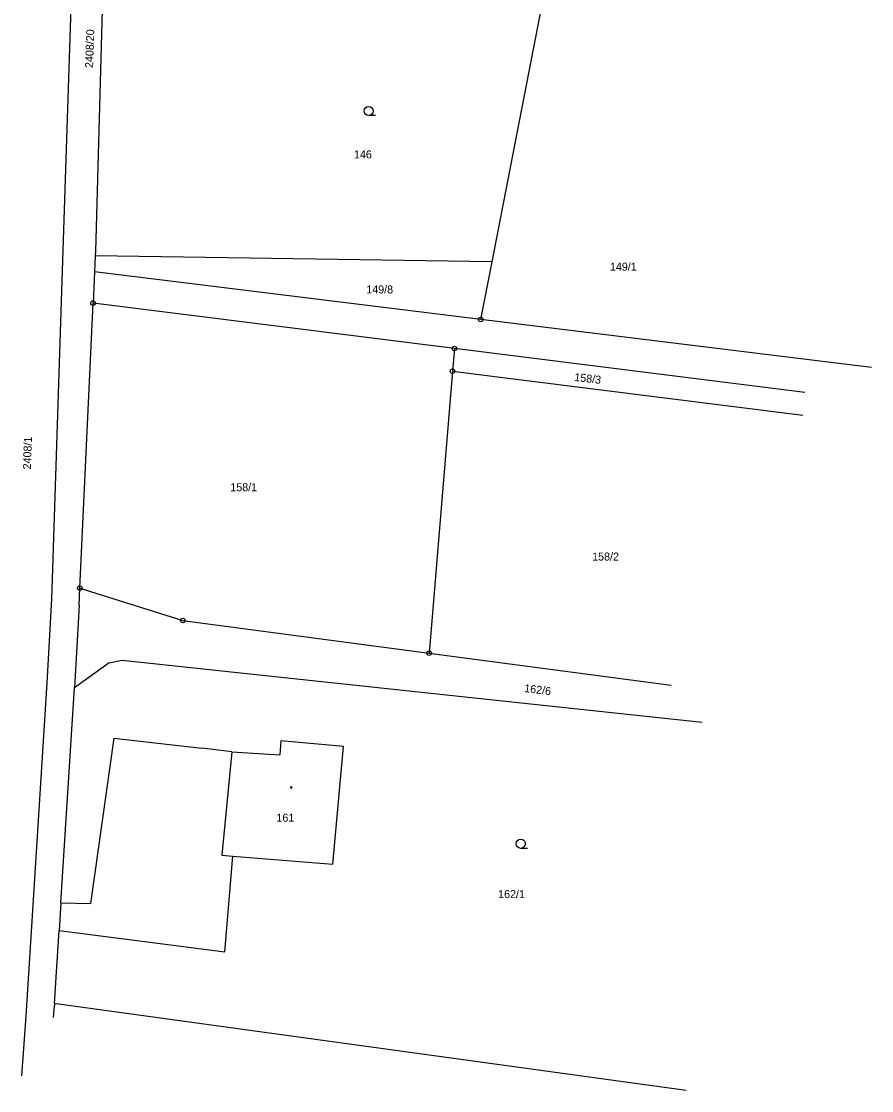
# Model space of a CAD drawing. Extents: x -454285 to -453563, y -1108687 to -1108249.
# Drawn here: x -453653.3 to -453578.9, y -1108665.2 to -1108571.7 of the extents above; entities that cross this region are included whole.
import ezdxf

# ---------------------------------------------------------------- set-up
doc = ezdxf.new("R2010")
doc.units = 0
for name, color, linetype in [('1', 7, 'Continuous'), ('14', 7, 'Continuous'), ('15', 7, 'Continuous'), ('16', 7, 'Continuous'), ('2', 7, 'Continuous'), ('23', 7, 'Continuous'), ('25', 7, 'Continuous'), ('28', 7, 'Continuous')]:
    doc.layers.add(name, color=color, linetype=linetype)

# ---------------------------------------------------------------- blocks, each defined once
blk = doc.blocks.new('Z402')
for start, end in [(0, 180), (180, 0)]:
    blk.add_arc((0, 0), 0.15, start, end)
blk = doc.blocks.new('Z105')
for radius in [0.5, 0.01]:
    blk.add_circle((0, 0), radius)
blk = doc.blocks.new('Z3040')
blk.add_line((1.5, 0), (0, 0))
blk.add_circle((0, 1), 1)

msp = doc.modelspace()

# ---------------------------------------------------------------- linework, layer by layer
at = {"layer": '1'}
for p, q in [((-453648.487, -1108555.791), (-453649.647, -1108591.661)), ((-453645.797, -1108555.891), (-453646.797, -1108591.781)), ((-453612.117, -1108592.681), (-453607.877, -1108570.931)), ((-453649.647, -1108591.661), (-453650.647, -1108622.191)), ((-453646.797, -1108591.781), (-453646.817, -1108592.171)), ((-453646.817, -1108592.171), (-453646.877, -1108593.571)), ((-453612.117, -1108592.681), (-453646.817, -1108592.171)), ((-453613.107, -1108597.731), (-453612.117, -1108592.681)), ((-453646.877, -1108593.571), (-453647.007, -1108596.291)), ((-453613.107, -1108597.731), (-453646.877, -1108593.571)), ((-453648.167, -1108621.231), (-453647.007, -1108596.291)), ((-453615.407, -1108600.261), (-453647.007, -1108596.291)), ((-453578.927, -1108601.941), (-453613.107, -1108597.731)), ((-453615.407, -1108600.261), (-453615.577, -1108602.251)), ((-453584.767, -1108604.111), (-453615.407, -1108600.261)), ((-453615.577, -1108602.251), (-453617.617, -1108626.911)), ((-453615.577, -1108602.251), (-453584.937, -1108606.101)), ((-453648.227, -1108622.701), (-453648.167, -1108621.231)), ((-453648.167, -1108621.231), (-453647.787, -1108621.351)), ((-453647.787, -1108621.351), (-453639.157, -1108624.051)), ((-453650.647, -1108622.191), (-453651.057, -1108629.511)), ((-453648.227, -1108622.701), (-453648.637, -1108629.941)), ((-453639.157, -1108624.051), (-453617.617, -1108626.911)), ((-453645.607, -1108627.761), (-453644.467, -1108627.531)), ((-453644.467, -1108627.531), (-453593.737, -1108632.961)), ((-453617.617, -1108626.911), (-453596.467, -1108629.721)), ((-453645.607, -1108627.761), (-453648.637, -1108629.941)), ((-453651.057, -1108629.511), (-453652.887, -1108658.661)), ((-453649.817, -1108648.741), (-453648.637, -1108629.941)), ((-453645.197, -1108634.341), (-453647.247, -1108648.801)), ((-453645.197, -1108634.341), (-453637.497, -1108635.231)), ((-453630.577, -1108634.581), (-453630.687, -1108635.811)), ((-453625.097, -1108635.081), (-453630.577, -1108634.581)), ((-453626.037, -1108645.361), (-453625.097, -1108635.081)), ((-453634.877, -1108635.531), (-453637.497, -1108635.231)), ((-453634.877, -1108635.531), (-453630.687, -1108635.811)), ((-453635.487, -1108653.041), (-453634.787, -1108644.671)), ((-453634.787, -1108644.671), (-453626.037, -1108645.361)), ((-453649.817, -1108648.741), (-453649.967, -1108651.181)), ((-453649.817, -1108648.741), (-453647.247, -1108648.801)), ((-453650.367, -1108657.561), (-453649.967, -1108651.181)), ((-453649.967, -1108651.181), (-453635.487, -1108653.041)), ((-453650.467, -1108658.781), (-453650.377, -1108657.761)), ((-453650.367, -1108657.561), (-453650.377, -1108657.761)), ((-453650.227, -1108657.581), (-453650.367, -1108657.561)), ((-453595.147, -1108665.171), (-453650.227, -1108657.581)), ((-453652.887, -1108658.661), (-453653.277, -1108663.891))]:
    msp.add_line(p, q, dxfattribs=at)
at = {"layer": '2'}
for p, q in [((-453634.877, -1108635.531), (-453635.737, -1108644.591)), ((-453635.737, -1108644.591), (-453634.787, -1108644.671))]:
    msp.add_line(p, q, dxfattribs=at)

# ---------------------------------------------------------------- block references
at = {"layer": '23', "xscale": 0.4, "yscale": 0.4000000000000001}
for p in [(-453622.907, -1108579.901), (-453609.607, -1108643.981)]:
    msp.add_blockref('Z3040', p, dxfattribs=at)
at = {"layer": '25', "xscale": 0.4, "yscale": 0.4000000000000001}
msp.add_blockref('Z402', (-453629.677, -1108638.651), dxfattribs=at)
at = {"layer": '28', "xscale": 0.4, "yscale": 0.4000000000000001}
for p in [(-453647.007, -1108596.291), (-453613.107, -1108597.731), (-453615.407, -1108600.261), (-453615.577, -1108602.251), (-453648.167, -1108621.231), (-453639.157, -1108624.051), (-453617.617, -1108626.911)]:
    msp.add_blockref('Z105', p, dxfattribs=at)

# ---------------------------------------------------------------- texts
at = {"layer": '14'}
for s, rotation, p in [('2408/20', 88.065, (-453647.011, -1108575.746)), ('158/3', 353.3456, (-453604.953, -1108603.095)), ('162/6', 353.115, (-453609.332, -1108630.309))]:
    msp.add_text(s, height=0.7, rotation=rotation, dxfattribs=at).set_placement(p)
for s, p in [('146', (-453624.193, -1108583.641)), ('149/1', (-453601.807, -1108593.461)), ('149/8', (-453623.113, -1108595.451)), ('158/1', (-453635.007, -1108612.751)), ('158/2', (-453603.363, -1108618.811)), ('162/1', (-453611.587, -1108648.331))]:
    msp.add_text(s, height=0.7, dxfattribs=at).set_placement(p)
at = {"layer": '15'}
msp.add_text('161', height=0.7, dxfattribs=at).set_placement((-453630.977, -1108641.651))
at = {"layer": '16'}
msp.add_text('2408/1', height=0.7, rotation=88.0585, dxfattribs=at).set_placement((-453652.447, -1108610.851))

doc.saveas('drawing.dxf')
